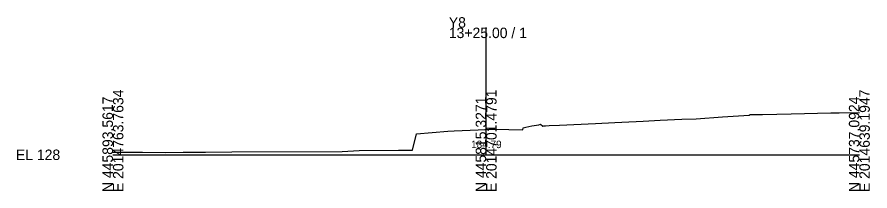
# Model space of a CAD drawing. Extents: x -26 to 1403, y -10 to 8043.
# Drawn here: x -25.7 to 202.8, y 6490.3 to 6536.9 of the extents above; entities that cross this region are included whole.
import ezdxf

# ---------------------------------------------------------------- set-up
doc = ezdxf.new("R2010")
doc.units = 0
for name, color, linetype in [('Default', 7, 'Continuous'), ('Exist Cross Section Cell', 7, 'Continuous'), ('Exist XS Center Line Elevation Label', 7, 'Continuous'), ('Exist XS Ground Line', 7, 'Continuous')]:
    doc.layers.add(name, color=color, linetype=linetype)

msp = doc.modelspace()

# ---------------------------------------------------------------- linework, layer by layer
at = {"layer": 'Exist Cross Section Cell'}
for p, q in [((100, 6500), (100, 6534.08)), ((0, 6500), (100, 6500)), ((100, 6500), (200, 6500))]:
    msp.add_line(p, q, dxfattribs=at)
at = {"layer": 'Exist XS Ground Line'}
msp.add_lwpolyline([(0, 6500.73), (6.01, 6500.67), (6.85, 6500.66), (7.9, 6500.66), (13.97, 6500.64), (18.8, 6500.67), (21.09, 6500.69), (24.84, 6500.74), (31.83, 6500.75), (61.41, 6500.89), (65.99, 6501.11), (76.53, 6501.27), (79.83, 6501.24), (80.29, 6501.25), (81.31, 6505.58), (89.75, 6506.3), (91.41, 6506.39), (100, 6506.79), (100.72, 6506.83), (101.58, 6506.86), (102.33, 6506.85), (109.82, 6506.68), (109.95, 6507.24), (110.61, 6507.38), (112.22, 6507.74), (114.11, 6508.02), (114.6, 6508.17), (115.18, 6507.71), (115.49, 6507.74), (115.92, 6507.76), (116.93, 6507.83), (119.69, 6507.94), (129.27, 6508.43), (134.48, 6508.68), (136.36, 6508.77), (142.08, 6509.01), (146.63, 6509.28), (152.42, 6509.51), (156.31, 6509.64), (163.36, 6510.13), (170.45, 6510.58), (170.79, 6510.77), (172.28, 6510.81), (172.6, 6510.82), (174.03, 6510.81), (181.74, 6510.98), (192.32, 6511.22), (194.62, 6511.29), (200, 6511.36)], dxfattribs=at)

# ---------------------------------------------------------------- texts
at = {"layer": 'Default'}
msp.add_text('-', height=0.0001, dxfattribs=at).set_placement((0, 6500))
at = {"layer": 'Exist Cross Section Cell'}
for s, p in [('Y8', (90, 6534.08)), ('13+25.00 / 1', (90, 6531.28)), ('EL 128', (-26, 6498.6))]:
    msp.add_text(s, height=2.8, dxfattribs=at).set_placement(p)
for s, p in [('E 2014763.7634', (2.8, 6490)), ('E 2014701.4791', (102.8, 6490)), ('N 445737.0924', (200, 6490)), ('E 2014639.1947', (202.8, 6490)), ('N 445893.5617', (0, 6490)), ('N 445815.3271', (100, 6490))]:
    msp.add_text(s, height=2.8, rotation=90, dxfattribs=at).set_placement(p)
at = {"layer": 'Exist XS Center Line Elevation Label'}
msp.add_text('134.79', height=2, dxfattribs=at).set_placement((95.97, 6501.79))

doc.saveas('drawing.dxf')
